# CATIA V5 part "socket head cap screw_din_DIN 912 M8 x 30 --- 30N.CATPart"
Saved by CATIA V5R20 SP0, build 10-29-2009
Part number: socket head cap screw_din_DIN 912 M8 x 30 --- 30N
Revision: ANY
Definition: UNKNOWN
Nomenclature: socket head cap screw_din_DIN 912 M8 x 30 --- 30N
Source: Unknown
Bounding box of the stored display mesh (mm): x 0 to 38, y -6.337 to 6.337, z -6.5 to 6.5
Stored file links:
  C:\Users\Utente\Desktop\IO LAVORO\3D X SITO CF\CUMSA\3D files CG\CG 754049\socket head cap screw_din_DIN 912 M8 x 30 --- 30N.CATPart
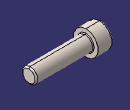
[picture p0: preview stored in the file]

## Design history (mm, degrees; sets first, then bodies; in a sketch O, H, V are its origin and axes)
Body1 "Hex" (main body)
  Solid1: solid without history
